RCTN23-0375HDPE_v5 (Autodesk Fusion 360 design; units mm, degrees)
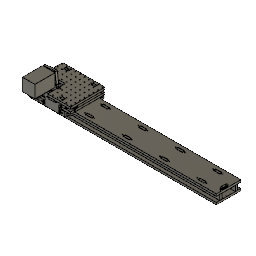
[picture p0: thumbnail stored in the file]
parameter "w_rail" = 110 comment "width of the rail - from 90 by 20mm increment"
parameter "l_gantry" = 190 comment "length of the travelling gantry - from 190 by 20mm increment"
parameter "l_travel" = 610 comment "total length of travel"
parameter "t_sheet_MAIN" = 9.525 (= "3 / 8 * 1") comment "thickness of *most* of the gantry material"
parameter "t_sheet_SECOND" = 9.525 (= "3 / 8 * 1") comment "thickness of the webs"
parameter "t_three" = 0.1
parameter "t_four" = 0.1
parameter "od_bearings" = 22
parameter "id_bearings" = 8
parameter "t_bearings" = 7
parameter "p_belt" = 2
parameter "w_belt" = 9
parameter "t_belt" = 1.4
parameter "t_meshedBelts" = 2.3
parameter "d_rail" = 25.4 (= "1")
parameter "d_beam" = 38.525 (= "od_bearings + t_sheet_MAIN + 2 mm + 5 mm") comment "min. is 2*t_bearings+3*shim+6mm+clearance"
parameter "hw_m6_drill" = 5 comment "5mm for zund bit"
parameter "r_cutoutTool" = 2.05 (= "4.1 mm / 2")
parameter "preload_flex_length" = 10
parameter "preload_flex_thickness" = 5
parameter "hw_m3_thru" = 3.25
parameter "hw_m3_head" = 5.5
parameter "hw_m3_washer" = 7
parameter "hw_m3_thread" = 2.5
parameter "tab_breather" = 0.2 comment "tab clearance"
parameter "hw_m5_thread" = 4.2
parameter "hw_m5_head" = 8.5
parameter "hw_m5_washer" = 10
parameter "hw_m5_thru" = 5.25
parameter "hw_m6_thru" = 6.5
parameter "hw_m6_head" = 10
parameter "hw_m6_washer" = 12
parameter "preload_displacement" = 0.25
parameter "dist_gap" = 4
parameter "l_beltblock" = 18
parameter "tab_breather_hdpe" = 0.1 (= "tab_breather / 2")
parameter "total_length" = 836 (= "l_gantry + l_travel + 2 * l_beltblock")
parameter "hw_plstf6_thread" = 2.94
parameter "hw_plstf6_thru" = 4
parameter "hw_plstf6_head" = 6.86
parameter "hw_plstf6_washer" = 7.92
parameter "t_beltroller_wall" = 1.7
parameter "hw_m3_flathead" = 6
parameter "d99" = 20
parameter "d124" = 14.2875 (= "t_sheet_MAIN * 1.5")
parameter "d129" = 3
parameter "d213" = 0.2 (= "tab_breather")
parameter "d732" = 0.5
parameter "d893" = 2.25
parameter "d940" = 5.75 (= "d939 / 2 + 2 mm")
sketch "Plan"
  dimension "d670" = 110 (= "w_rail")
  dimension "d671" = 836 (= "l_travel + l_gantry + 2 * l_beltblock")
  dimension "d672" = 190 (= "l_gantry")
  dimension "d673" = 22 (= "od_bearings")
  dimension "d674" = 18 (= "l_beltblock")
  dimension "d675" = 22 (= "od_bearings")
  dimension "d676" = 20
  dimension "d677" = 7 (= "t_bearings")
  dimension "d678" = 22 (= "od_bearings")
  dimension "d679" = 9.525 (= "t_sheet_SECOND")
  dimension "d680" = 8
  dimension "d681" = 9.525 (= "t_sheet_MAIN")
  dimension "d682" = 1
  dimension "d683" = 1
  dimension "d684" = 5
  dimension "d765" = 9.525 (= "t_sheet_MAIN")
  dimension "d766" = 1 (= "d682")
extrude "Extrude81" new body sketch "Plan" no distance stored bodies "Top Rail Plate"
extrude "Extrude82" new body sketch "Plan" blind 9.525 (= "t_sheet_MAIN") from offset 4 (= "dist_gap")
extrude "Extrude83" new body sketch "Plan" blind 23 (= "od_bearings + 1 mm") bodies "Fixed Side Plate", "Floating Side Plate"
extrude "Extrude84" add sketch "Plan" no distance stored
sketch "Fixed Side" plane through (0, 120.525, 0) normal (0, 1, 0) x axis (-1, 0, 0)
  dimension "d694" = 22 (= "od_bearings")
  dimension "d696" = 9.525 (= "t_sheet_MAIN")
  dimension "d697" = 0.25 (= "preload_displacement")
  dimension "d699" = 9.525 (= "t_sheet_MAIN")
  dimension "d701" = 4 (= "dist_gap")
  dimension "d704" = 5 (= "hw_m6_drill")
  dimension "d706" = 7.92 (= "hw_plstf6_washer")
  dimension "d707" = 4.21 (= "hw_plstf6_washer / 2 + 0.25 mm")
  dimension "d711" = 26 (= "od_bearings + 4 mm")
  dimension "d713" = 5 (= "hw_m6_drill")
  dimension "d714" = 13
  dimension "d716" = 5 (= "preload_flex_thickness")
  dimension "d717" = 5 (= "preload_flex_thickness")
  dimension "d718" = 10 (= "preload_flex_length")
  dimension "d719" = 7
  dimension "d733" = 0.5
  dimension "d755" = 4 (= "hw_plstf6_thru")
  dimension "d756" = 0.2 (= "tab_breather")
  dimension "d759" = 20
  dimension "d776" = 11.5
  dimension "d1008" = 9
  dimension "d1009" = 3.5 (= "hw_m3_washer / 2")
  dimension "d1014" = 6
  dimension "d1141" = 25
  dimension "d1142" = 2
  dimension "d1167" = 9.025 (= "t_sheet_MAIN - 0.5 mm")
  dimension "d1168" = 14.2875 (= "t_sheet_MAIN * 1.5")
  dimension "d1169" = 45
  dimension "d1170" = 4.1 (= "r_cutoutTool * 2")
extrude "Extrude85" cut sketch "Fixed Side" no distance stored
extrude "Extrude86" cut sketch "Fixed Side" no distance stored
extrude "Extrude87" sketch "Fixed Side" blind -16 (= "-t_bearings - 6 mm - 2 mm - 1 mm")
extrude "Extrude88" sketch "Fixed Side" blind 21 (= "od_bearings - 1 mm")
extrude "Extrude93" sketch "Fixed Side" blind 9.525 (= "t_sheet_MAIN")
extrude "Extrude144" add sketch "Fixed Side" no distance stored
extrude "Extrude145" cut sketch "Fixed Side" no distance stored
combine "Combine17"
offset_faces "OffsetFaces3"
combine "Combine16"
offset_faces "OffsetFaces4"
extrude "Extrude89" sketch "Fixed Side" no distance stored from offset -1
sketch "Fixed Top" plane through (0, 0, 13.525) normal (0, 0, 1) x axis (-1, 0, 0)
  dimension "d752" = 22 (= "od_bearings")
  dimension "d753" = 5 (= "hw_m6_drill")
  dimension "d767" = 7 (= "hw_m3_washer")
  dimension "d768" = 2.5 (= "hw_m3_thread")
  dimension "d1004" = 13
  dimension "d1010" = 3.75 (= "hw_m3_washer / 2 + 0.25 mm")
  dimension "d1011" = 8
extrude "Extrude91" cut sketch "Fixed Top" no distance stored
extrude "Extrude102" sketch "Fixed Top" no distance stored from offset -3
extrude "Extrude124" sketch "Fixed Top" blind -6 from offset 1
sketch "Floating Side" plane through (0, -10.525, 0) normal (0, -1, 0) x axis (1, 0, 0)
  dimension "d777" = 9.525 (= "t_sheet_MAIN")
  dimension "d778" = 4 (= "dist_gap")
  dimension "d779" = 9.525 (= "t_sheet_MAIN")
  dimension "d780" = 0.25 (= "preload_displacement")
  dimension "d781" = 22 (= "od_bearings")
  dimension "d783" = 12
  dimension "d784" = 7.92 (= "hw_plstf6_washer")
  dimension "d785" = 4 (= "hw_plstf6_thru")
  dimension "d786" = 4.46 (= "hw_plstf6_washer / 2 + 0.5 mm")
  dimension "d787" = 6
  dimension "d789" = 5 (= "hw_m6_drill")
  dimension "d790" = 5 (= "preload_flex_thickness")
  dimension "d791" = 5 (= "preload_flex_thickness")
  dimension "d792" = 6.5
  dimension "d793" = 10 (= "preload_flex_length")
  dimension "d794" = 0.5
  dimension "d796" = 9
  dimension "d797" = 45
  dimension "d835" = 7 (= "hw_m3_head + 1.5 mm")
  dimension "d1175" = 9.025 (= "t_sheet_MAIN - 0.5 mm")
  dimension "d1176" = 14.2875 (= "t_sheet_MAIN * 1.5")
  dimension "d1177" = 4.1 (= "r_cutoutTool * 2")
  dimension "d1178" = 45
extrude "Extrude94" cut sketch "Floating Side" no distance stored
extrude "Extrude95" sketch "Floating Side" blind 21 (= "od_bearings - 1 mm")
extrude "Extrude96" sketch "Floating Side" blind -16
extrude "Extrude146" add sketch "Floating Side" no distance stored
extrude "Extrude147" cut sketch "Floating Side" no distance stored
combine "Combine18"
offset_faces "OffsetFaces5"
sketch "Floating Top" plane through (0, 0, 13.525) normal (0, 0, 1) x axis (-1, 0, 0)
  dimension "d808" = 22 (= "od_bearings")
  dimension "d809" = 5 (= "hw_m6_drill")
  dimension "d810" = 10 (= "preload_flex_length")
  dimension "d814" = 5.5
  dimension "d825" = 4
  dimension "d826" = 5 (= "preload_flex_thickness")
  dimension "d827" = 7
  dimension "d828" = 7 (= "3 mm + 2 mm + 2 mm")
  dimension "d829" = 4.2 (= "r_cutoutTool * 2 + 0.1 mm")
  dimension "d830" = 5 (= "preload_flex_thickness")
  dimension "d831" = 5
  dimension "d832" = 1
  dimension "d833" = 5.5 (= "hw_m3_head")
  dimension "d834" = 2.5 (= "hw_m3_thread")
  dimension "d851" = 0.25 (= "preload_displacement")
  dimension "d1164" = 1
extrude "Extrude98" cut sketch "Floating Top" no distance stored
fillet "Fillet66" radius 1
offset_faces "OffsetFaces6"
extrude "Extrude99" sketch "Floating Side" blind 9.525 (= "t_sheet_MAIN")
extrude "Extrude100" sketch "Floating Side" no distance stored from offset -1
extrude "Extrude101" sketch "Floating Top" no distance stored from offset -3
fillet "Fillet46" radius 2.05 (= "r_cutoutTool")
sketch "Sketch37" plane through (0, 120.525, 0) normal (0, 1, 0) x axis (-1, 0, 0)
  dimension "d854" = 4.1 (= "r_cutoutTool * 2")
  dimension "d955" = 45
extrude "Extrude103" cut sketch "Sketch37" no distance stored
sketch "Sketch38" plane through (0, 0, 13.525) normal (0, 0, 1) x axis (-1, 0, 0)
  dimension "d858" = 45
  dimension "d859" = 4.1 (= "r_cutoutTool * 2")
  dimension "d862" = 4.1 (= "r_cutoutTool * 2")
  dimension "d863" = 45
extrude "Extrude104" cut sketch "Sketch38" no distance stored
sketch "Sketch39" plane through (0, -10.525, 0) normal (0, -1, 0) x axis (1, 0, 0)
  dimension "d865" = 4.1 (= "r_cutoutTool * 2")
  dimension "d1001" = 45
extrude "Extrude105" cut sketch "Sketch39" no distance stored
fillet "Fillet47" radius 0.5
fillet "Fillet67" radius 2
fillet "Fillet48" radius 4
sketch "Sketch52" plane through (0, 0, 23) normal (0, 0, 1) x axis (-1, 0, 0)
  dimension "d1183" = 0.5
  dimension "d1184" = 0.5
  dimension "d1185" = 0.2 (= "tab_breather")
  dimension "d1186" = 0.2 (= "d1185")
  dimension "d1187" = 0.2 (= "d1185")
  dimension "d1188" = 0.2 (= "d1185")
  dimension "d1189" = 0.2 (= "tab_breather")
  dimension "d1190" = 0.2 (= "d1189")
  dimension "d1191" = 0.2 (= "d1189")
  dimension "d1192" = 0.2 (= "d1189")
  dimension "d1193" = 4.1 (= "r_cutoutTool * 2")
  dimension "d1194" = 45
  dimension "d1195" = 3.25 (= "hw_m3_thru")
  dimension "d1196" = 6
  dimension "d1197" = 7 (= "hw_m3_washer")
  dimension "d1198" = 45
  dimension "d1199" = 4.1 (= "r_cutoutTool * 2")
  dimension "d1200" = 6 (= "d1196")
  dimension "d1201" = 4 (= "hw_plstf6_thru")
extrude "Extrude148" new body sketch "Sketch52" along normal blind 9.525 (= "t_sheet_MAIN") bodies "Top Plate"
fillet "Fillet69" radius 1
fillet "Fillet70" radius 1
fillet "Fillet68" radius 4
mirror "Mirror22"
combine "Combine19"
combine "Combine20"
combine "Combine21"
mirror "Mirror26"
combine "Combine25"
sketch "Motor Base" plane through (0, 0, 13.525) normal (0, 0, 1) x axis (-1, 0, 0)
  dimension "d873" = 25.4 (= "od_bearings + ( t_beltroller_wall * 2 )")
  dimension "d874" = 2
  dimension "d875" = 7 (= "t_bearings")
  dimension "d876" = 7 (= "t_bearings")
  dimension "d877" = 0.75
  dimension "d878" = 6.3662 (= "( nt_pinion * 2 / PI ) * 1 mm / 2")
  dimension "d879" = 75
  dimension "d883" = 5
  dimension "d885" = 2.5 (= "hw_m3_thread")
  dimension "d930" = 3.5
  dimension "d958" = 3.5 (= "d930")
  dimension "d1093" = 11 (= "od_bearings / 2")
  dimension "d1094" = 0.7 (= "d874 / 2 - 0.3 mm")
  dimension "d1095" = 2
  dimension "d1096" = 45
  dimension "d1097" = 0.3
  dimension "d1098" = 5 (= "w_belt / 2 + 0.5 mm")
  dimension "d1099" = 0.5
  dimension "d1100" = 2.05 (= "t_meshedBelts - 0.25 mm")
  dimension "d1207" = 6 (= "hw_m3_flathead")
  dimension "d1208" = 13
  dimension "d1209" = 3.25 (= "hw_m3_thru")
  dimension "d1212" = 4.1 (= "r_cutoutTool * 2")
  dimension "d1213" = 45
  dimension "d1214" = 4.5
  dimension "d1215" = 4.5 (= "d1214")
  dimension "d1216" = 9.725 (= "t_sheet_MAIN + tab_breather")
  dimension "d1217" = 1
  dimension "d1218" = 9.45 (= "8 mm + 1.45 mm")
  dimension "d1260" = 5
  dimension "d1264" = 3
  dimension "d1265" = 5
extrude "Extrude119" cut sketch "Motor Base" no distance stored
extrude "Extrude149" cut sketch "Motor Base" to an object
sketch "Sketch53"
  dimension "d1219" = 9.525 (= "t_sheet_MAIN")
  dimension "d1220" = 0.1 (= "tab_breather / 2")
  dimension "d1221" = 0.1 (= "tab_breather / 2")
  dimension "d1222" = 0.1 (= "tab_breather / 2")
extrude "Extrude150" sketch "Sketch53" to an object from offset 0.5 bodies "Motor Plate"
extrude "Extrude151" sketch "Sketch53" to an object
combine "Combine26"
sketch "Motor" plane through (0, 29.625, 0) normal (0, 1, 0) x axis (-1, 0, 0)
  dimension "d900" = 4.1 (= "r_cutoutTool * 2")
  dimension "d901" = 25.4 (= "od_bearings + t_beltroller_wall * 2")
  dimension "d902" = 5 (= "hw_m6_drill")
  dimension "d903" = 12.7324 (= "( nt_pinion * 2 / PI ) * 1 mm")
  dimension "d905" = 0.75
  dimension "d906" = 45
  dimension "d907" = 56.4
  dimension "d908" = 47.14
  dimension "d1103" = 2 (= "t_meshedBelts - 0.3 mm")
  dimension "d1117" = 22 (= "od_bearings")
  dimension "d1118" = 2
  dimension "d1231" = 2.3 (= "t_meshedBelts")
  dimension "d1232" = 45
  dimension "d1233" = 45
  dimension "d1234" = 4.2 (= "hw_m5_thread")
  dimension "d1235" = 8
  dimension "d1236" = 2
  dimension "d1237" = 2.625 (= "hw_m5_thru / 2")
  dimension "d1238" = 19.075 (= "( 38.15 / 2 ) * 1 mm")
  dimension "d1239" = 2 (= "d1236")
  dimension "d1240" = 8 (= "d1235")
  dimension "d1241" = 8 (= "d1235")
  dimension "d1242" = 2 (= "d1236")
  dimension "d1243" = 10 (= "hw_m5_washer")
  dimension "d1244" = 5
  dimension "d1245" = 10 (= "hw_m5_washer")
  dimension "d1246" = 11
  dimension "d1247" = 70
  dimension "d1248" = 70 (= "d1247")
  dimension "d1249" = 1
extrude "Extrude152" add sketch "Motor" no distance stored
fillet "Fillet71" radius 3
fillet "Fillet72" radius 4
fillet "Fillet73" radius 12
extrude "Extrude153" cut sketch "Motor" no distance stored
extrude "Extrude154" sketch "Motor Base" to an object
fillet "Fillet74" radius 0.5
fillet "Fillet75" radius 2
fillet "Fillet76" radius 0.5
extrude "Extrude137" sketch "Motor" to an object bodies "Belt Tender"
extrude "Extrude138" sketch "Motor" to an object
extrude "Extrude139" sketch "Motor" to an object
chamfer "Chamfer1" distance 0.4
fillet "Fillet65" radius 0.3
extrude "Extrude114" new body sketch "Motor" blind 16 (= "t_bearings * 2 + 2 mm") from offset 1
extrude "Extrude112" sketch "Motor" blind -90 bodies "Motor"
sketch "Belt Block" plane through (0, 0, 0) normal (0, 0, 1) x axis (-1, 0, 0)
  dimension "d935" = 9.5 (= "w_belt + 0.5 mm")
  dimension "d937" = 5.5 (= "hw_m3_head")
  dimension "d939" = 7.5 (= "hw_m3_head + 2 mm")
  dimension "d942" = 3.25 (= "hw_m3_thru")
  dimension "d943" = 2.5 (= "hw_m3_thread")
  dimension "d1030" = 2.1 (= "( 4.2 / 2 ) * 1 mm")
  dimension "d1031" = 0.5
  dimension "d1032" = 3.5
  dimension "d1033" = 3.75 (= "d939 / 2")
  dimension "d1034" = 4.75 (= "d1033 + 1 mm")
  dimension "d1035" = 13
  dimension "d1037" = 4
  dimension "d1040" = 4
  dimension "d1042" = 1.1
  dimension "d1061" = 14.7 (= "1 / 2 * 1  + 2 mm")
  dimension "d1266" = 7.5 (= "d939")
  dimension "d1267" = 4 (= "d1037")
extrude "Extrude115" cut sketch "Belt Block" no distance stored
work_plane "WorkPlane6"
mirror "Mirror24"
extrude "Extrude116" new body sketch "Belt Block" along normal blind 2.5 (= "t_meshedBelts + 0.2 mm") bodies "Belt Tension Tside 1"
extrude "Extrude117" sketch "Belt Block" blind 6 (= "4 mm + 2 mm")
extrude "Extrude126" new body sketch "Belt Block" no distance stored
extrude "Extrude127" new body sketch "Belt Block" to an object Side2Offset 0 bodies "Belt Tension Tside 2"
combine "Combine24"
fillet "Fillet62" radius 1
sketch "Sketch48" plane through (-14.7, 0, 0) normal (-1, 0, 0) x axis (0, -1, 0)
  dimension "d1055" = 2.94 (= "hw_plstf6_thread")
  dimension "d1056" = 4 (= "hw_plstf6_thru")
  dimension "d1062" = 6.86 (= "hw_plstf6_head")
  dimension "d1072" = 2.75
  dimension "d1073" = 6
extrude "Extrude128" cut sketch "Sketch48" to an object offset 1
extrude "Extrude129" cut sketch "Sketch48" to an object
extrude "Extrude130" cut sketch "Sketch48" to an object
extrude "Extrude131" cut sketch "Sketch48" to an object
sketch "Sketch50" plane through (0, 0, 0) normal (0, 0, 1) x axis (-1, 0, 0)
  dimension "d1079" = 4.2
  dimension "d1081" = 9.5
  dimension "d1091" = 5
  dimension "d1092" = 4.25
extrude "Extrude134" new body sketch "Sketch50" to an object bodies "Belt Tension OSide1"
extrude "Extrude135" sketch "Sketch50" blind 2
extrude "Extrude140" sketch "Sketch50" to an object bodies "Belt Tension OSide2"
extrude "Extrude141" sketch "Sketch50" to an object from offset 1.2
fillet "Fillet64" radius 4
sketch "Sketch45" plane through (0, 0, 0) normal (0, 0, 1) x axis (-1, 0, 0)
  dimension "d964" = 9.525 (= "t_sheet_SECOND")
  dimension "d965" = 14 (= "t_bearings + 7 mm")
  dimension "d966" = 0.1 (= "tab_breather_hdpe")
  dimension "d967" = 0.1 (= "d966")
  dimension "d968" = 0.1 (= "d966")
  dimension "d969" = 0.1 (= "d966")
  dimension "d971" = 28.575 (= "t_sheet_MAIN * 3")
  dimension "d972" = 4 (= "hw_plstf6_thru")
  dimension "d973" = 6
  dimension "d974" = 6 (= "d973")
  dimension "d976" = 45
  dimension "d977" = 4.1 (= "r_cutoutTool * 2")
  dimension "d1269" = 45
  dimension "d1270" = 20
  dimension "d1271" = 167.2 (= "total_length / num_tabs")
work_plane "WorkPlane5"
extrude "Extrude121" sketch "Sketch45" blind -12 (= "-( od_bearings + 2 mm ) / 2") bodies "Web 1"
extrude "Extrude120" cut sketch "Sketch45" no distance stored
fillet "Fillet58" radius 0.5
rectangular_pattern "R-Pattern7" vSpaceDistance 0
extrude "Extrude122" sketch "Sketch45" blind 8.525 (= "t_sheet_MAIN - 1 mm")
sketch "Sketch46" plane through (0, 15.2375, 0) normal (0, -1, 0) x axis (1, 0, 0)
  dimension "d989" = 4.1 (= "r_cutoutTool * 2")
  dimension "d1311" = 45
  dimension "d1312" = 90
extrude "Extrude155" cut sketch "Sketch46" no distance stored
fillet "Fillet57" radius 1
fillet "Fillet77" radius 0.5
rectangular_pattern "R-Pattern6" uSpaceDistance 167.2 (= "total_length / num_tabs") vSpaceDistance 0 bodies "Web 1 (1)", "Web 1 (2)", "Web 1 (3)", "Web 1 (4)"
mirror "Mirror27"
combine "Combine27" bodies "Web 1 (1)", "Web 1 (2)", "Web 1 (3)", "Web 1 (4)"
mirror "Mirror28" bodies "Web 1 (1)"
mirror "Mirror29" bodies "Web 1 (2)", "Web 1 (1) (1)", "Top Rail Plate (1)"
combine "Combine28" bodies "Web 1 (1) (1)"
combine "Combine29" bodies "Web 1 (2)"
sketch "Sketch54" plane through (0, 0, 32.525) normal (0, 0, 1) x axis (-1, 0, 0)
  dimension "d1288" = 4.2 (= "hw_m5_thread")
  dimension "d1289" = 7.5
  dimension "d1290" = 5
  dimension "d1291" = 10 (= "hw_m5_washer")
extrude "Extrude156" cut sketch "Sketch54" no distance stored
rectangular_pattern "R-Pattern8" countU 10 uSpaceDistance 20 vSpaceDistance 20
sketch "Sketch55" plane through (0, 0, -43.05) normal (0, 0, -1) x axis (1, 0, 0)
  dimension "d1298" = 4.2 (= "hw_m5_thread")
  dimension "d1299" = 5
  dimension "d1300" = 5
extrude "Extrude157" cut sketch "Sketch55" no distance stored
extrude "Extrude158" add sketch "Sketch55" no distance stored
rectangular_pattern "R-Pattern9" uSpaceDistance 20 vSpaceDistance -20
named bodies: "Top Rail Plate", "Plate", "Fixed Side Plate", "Floating Side Plate", "Motor", "Belt Tension Tside 1", "Web 1", "Body192 (1)", "Body192 (2)", "Body192 (3)", "Body192 (4)", "Body192 (5)", "Body192 (6)", "Body192 (7)", "Body192 (8)", "Body192 (9)", "Body192 (10)", "Body192 (11)", "Body192 (12)", "Body192 (13)", "Body192 (14)", "Body192 (15)", "Body192 (16)", "Belt Tension Tside 2", "Belt Tension OSide1", "Belt Tender", "Belt Tension OSide2", "Rail (2) (1)", "Rail (2) (2)", "Rail (2) (2) (1)", "Top Plate", "Motor Plate", "Web 1 (1)", "Web 1 (2)", "Web 1 (3)", "Web 1 (4)", "Web 1 (1) (1)", "Top Rail Plate (1)"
